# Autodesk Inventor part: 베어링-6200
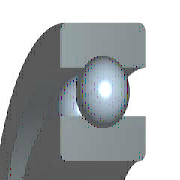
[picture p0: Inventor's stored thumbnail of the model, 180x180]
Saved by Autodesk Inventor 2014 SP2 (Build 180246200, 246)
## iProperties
Created: 2012-02
Part Number: 베어링-6200
Material: 강철, 연강
Description: 깊은 그루브 볼 베어링
Document SubType Name: Modeling
Standard: KS B 2023
Designer: mduedu
Standards Organization: KS
Language: ko-KR
Size Designation: 6200 - 10 x 30 x 9
Categories: <MemberInstance><Categories><Category DisplayName="샤프트 부품" InternalName="7f7aeb1f-a693-4053-b835-cee3144e0d98" Mnemonic="SHFT"><Category DisplayName="베어링" Inter
Density: 1 g/cm^3
Appearance: 노란색
IsCustomPart: 1
Author: mduedu
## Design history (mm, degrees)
sketch "스케치" dims "d0" = 5.2 (= -0.26 x WD + 0.26 x BD)
  geometry: L1 (1.9, 10)-(7.1, 10); L2 (4.5, 10)-(4.5, 7.4); L3 (4.5, 10)-(4.5, 12.6); L4 (2.568, 8.26)-(0, 8.26); L5 (0, 5)-(9, 5); L6 (2.568, 11.74)-(0, 11.74); L7 (0, 15)-(9, 15); L8 (9, 5)-(9, 8.26); L9 (6.432, 8.26)-(9, 8.26); L10 (6.432, 11.74)-(9, 11.74); L11 (9, 15)-(9, 11.74); L12 (-1.4, 0)-(8.4, 0) reference; L13 (0, -0.3)-(0, 5.3) reference
  constraints: 22 end point, 4 point on line, 2 collinear, 2 perpendicular, 2 symmetric about line, 1 midpoint, 1 parallel, 14 other
  dimensions: "d9" = 10 diameter of L5 L12 (= WD); "d11" = 30 diameter of L7 L12 (= BD); "d12" = 9 distance between parallel lines of L8 L13 (= KB); "d13" = 16.52 diameter of L9 L12 (= 0.326 x BD + 0.674 x WD)
revolve "본체" stored, may be unused: angle "d6" = 90 deg
revolve "볼" stored, may be unused: angle "d7" = 90 deg
pattern_circular "IDS_ARRAYBALL[SIMPL:T]" dims angle "d3" = 360 deg
body "Solid1"
fillet "모깎기1" dims "d1" = 0.6 (= KRS)
other parameters: "WD" = 10 [user parameter; used in 5 equation terms], "BD" = 30 [user parameter; used in 5 equation terms], "KB" = 9 [user parameter; used in 1 equation term], "KRS" = 0.6 [user parameter; used in 1 equation term], "d4" = 0, "d5" = 0, "d8" = 0, "d14" = 0, "d15" = 0, "BBA" = 0 [user parameter], "BC0" = 2360000 [user parameter], "BC" = 5070000 [user parameter], "BR" = 15 (= 0.5 x BD) [user parameter], "WR" = 5 (= 0.5 x WD) [user parameter]
